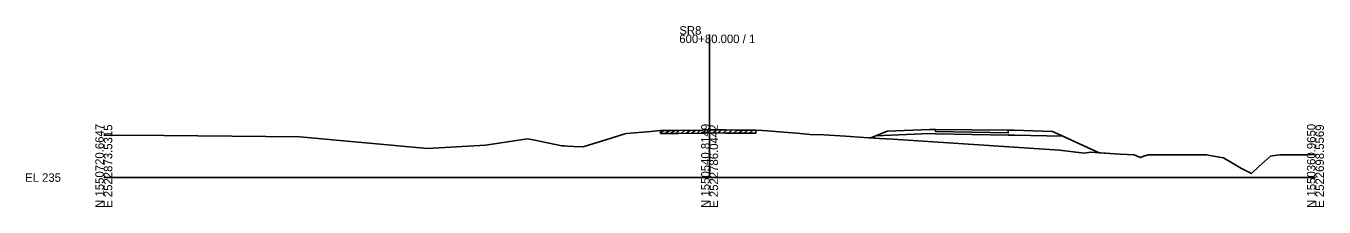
# Model space of a CAD drawing. Extents: x -26 to 2803, y -10 to 19537.
# Drawn here: x -25.7 to 402.8, y 8990.3 to 9049.9 of the extents above; entities that cross this region are included whole.
import ezdxf

# ---------------------------------------------------------------- set-up
doc = ezdxf.new("R2010")
doc.units = 0
for name, color, linetype in [('50', 7, 'Continuous'), ('XS_CELL', 7, 'Continuous'), ('XS_M_MULTI', 7, 'Continuous'), ('XS_M_SHAPES_EARTHWORK', 7, 'Continuous'), ('XS_P_FINISHED_GRADE', 7, 'Continuous'), ('XS_P_SUBGRADE_GRANULAR', 7, 'Continuous'), ('XS_P_SUBGRADE_PAVEMENT', 7, 'Continuous'), ('XS_X_GROUND', 7, 'Continuous')]:
    doc.layers.add(name, color=color, linetype=linetype)

msp = doc.modelspace()

# ---------------------------------------------------------------- linework, layer by layer
at = {"layer": '50'}
for p, q in [((183.74, 9014.48), (184.91, 9015.5)), ((183.74, 9014.48), (183.74, 9015.48)), ((183.74, 9014.48), (189.6, 9014.56)), ((185.47, 9014.5), (186.64, 9015.52)), ((187.2, 9014.53), (188.37, 9015.54)), ((188.93, 9014.55), (190.1, 9015.57)), ((189.6, 9014.56), (197.81, 9014.67)), ((190.66, 9014.57), (191.83, 9015.59)), ((192.39, 9014.6), (193.56, 9015.61)), ((194.12, 9014.62), (195.29, 9015.64)), ((195.85, 9014.65), (197.02, 9015.66)), ((197.58, 9014.67), (198.75, 9015.68)), ((197.81, 9014.67), (198.84, 9014.69)), ((198.84, 9014.69), (199.58, 9014.7)), ((199.31, 9014.69), (200.46, 9015.69)), ((199.58, 9014.7), (200, 9014.69)), ((200, 9014.69), (205.27, 9014.68)), ((201.04, 9014.69), (202.18, 9015.69)), ((202.77, 9014.69), (203.91, 9015.68)), ((204.5, 9014.68), (205.64, 9015.68)), ((205.27, 9014.68), (209, 9014.67)), ((206.22, 9014.67), (207.37, 9015.67)), ((207.95, 9014.67), (209.1, 9015.67)), ((209, 9014.67), (211.46, 9014.66)), ((209.68, 9014.66), (210.83, 9015.66)), ((211.41, 9014.66), (212.56, 9015.66)), ((211.46, 9014.66), (215.27, 9014.65)), ((213.14, 9014.65), (214.29, 9015.65)), ((215.27, 9015.65), (215.27, 9014.65))]:
    msp.add_line(p, q, dxfattribs=at)
at = {"layer": 'XS_CELL'}
for p, q in [((200, 9000), (200, 9047.09)), ((0, 9000), (200, 9000)), ((200, 9000), (400, 9000))]:
    msp.add_line(p, q, dxfattribs=at)
at = {"layer": 'XS_M_MULTI'}
for p, q in [((253.19, 9013.08), (258.62, 9015.34)), ((258.62, 9015.34), (272.75, 9015.83)), ((272.75, 9015.83), (286.6, 9015.7)), ((286.6, 9015.7), (300.46, 9015.59)), ((300.46, 9015.59), (313.17, 9015.15)), ((313.17, 9015.15), (328.58, 9008.19))]:
    msp.add_line(p, q, dxfattribs=at)
for points in [[(0, 9014.01), (19.82, 9013.88), (64.74, 9013.38), (106.88, 9009.59), (126.02, 9010.7), (139.91, 9012.73), (141.73, 9012.46), (151.22, 9010.47), (151.57, 9010.45), (152.11, 9010.42), (153.06, 9010.37), (155.18, 9010.25), (158.31, 9010.08), (160.39, 9010.76), (165.75, 9012.47), (171.7, 9014.3), (172.09, 9014.42), (172.59, 9014.57), (180.57, 9015.22), (183.74, 9015.48), (189.6, 9015.56), (197.81, 9015.67), (198.84, 9015.69), (199.58, 9015.7), (200, 9015.69), (205.27, 9015.68), (209, 9015.67), (211.46, 9015.66), (215.27, 9015.65), (217.43, 9015.48), (219.06, 9015.35), (223.08, 9015.04), (228.76, 9014.62), (233.22, 9014.23), (237.68, 9014.06), (244.91, 9013.6), (250.96, 9013.22), (253.19, 9013.08)], [(328.58, 9008.19), (335.55, 9007.76), (340.21, 9007.48), (342.21, 9006.57), (343.01, 9006.91), (344.82, 9007.5), (349.87, 9007.44), (364.15, 9007.48), (365.19, 9007.29), (369.66, 9006.49), (375.63, 9003.02), (378.86, 9001.3), (381.29, 9003.69), (385.22, 9007.06), (385.73, 9007.13), (388.27, 9007.49), (397.2, 9007.52), (400, 9007.58)]]:
    msp.add_lwpolyline(points, dxfattribs=at)
at = {"layer": 'XS_M_SHAPES_EARTHWORK'}
for points in [[(256.09, 9012.9), (260.5, 9012.62), (315.52, 9009.01), (323.65, 9008.06), (325.89, 9008.35), (328.58, 9008.19), (316.58, 9013.61), (300.6, 9013.92), (298.6, 9013.96), (286.6, 9014.2), (274.6, 9014.44), (272.6, 9014.48), (254.86, 9013.77), (253.19, 9013.08)], [(300.6, 9013.92), (316.58, 9013.61), (313.17, 9015.15), (300.46, 9015.59), (298.6, 9015.6), (298.6, 9014.71), (286.6, 9014.95), (274.6, 9015.19), (274.6, 9015.81), (272.75, 9015.83), (258.62, 9015.34), (254.86, 9013.77), (272.6, 9014.48), (274.6, 9014.44), (286.6, 9014.2), (298.6, 9013.96)], [(286.6, 9014.95), (298.6, 9014.71), (298.6, 9015.6), (286.6, 9015.7), (274.6, 9015.81), (274.6, 9015.19)]]:
    msp.add_lwpolyline(points, close=True, dxfattribs=at)
at = {"layer": 'XS_P_FINISHED_GRADE'}
for p, q in [((258.62, 9015.34), (253.19, 9013.08)), ((272.75, 9015.83), (258.62, 9015.34)), ((272.75, 9015.83), (286.6, 9015.7)), ((286.6, 9015.7), (300.46, 9015.59)), ((300.46, 9015.59), (313.17, 9015.15)), ((313.17, 9015.15), (328.58, 9008.19))]:
    msp.add_line(p, q, dxfattribs=at)
at = {"layer": 'XS_P_SUBGRADE_GRANULAR'}
for p, q in [((272.6, 9014.48), (254.86, 9013.77)), ((274.6, 9014.44), (272.6, 9014.48)), ((274.6, 9014.44), (286.6, 9014.2)), ((286.6, 9014.2), (298.6, 9013.96)), ((298.6, 9013.96), (300.6, 9013.92)), ((300.6, 9013.92), (316.58, 9013.61))]:
    msp.add_line(p, q, dxfattribs=at)
at = {"layer": 'XS_P_SUBGRADE_PAVEMENT'}
for p, q in [((274.6, 9015.19), (274.6, 9015.81)), ((274.6, 9015.19), (286.6, 9014.95)), ((286.6, 9014.95), (298.6, 9014.71)), ((298.6, 9014.71), (298.6, 9015.6))]:
    msp.add_line(p, q, dxfattribs=at)
at = {"layer": 'XS_X_GROUND'}
msp.add_lwpolyline([(0, 9014.01), (19.82, 9013.88), (64.74, 9013.38), (106.88, 9009.59), (126.02, 9010.7), (139.91, 9012.73), (141.73, 9012.46), (151.22, 9010.47), (151.57, 9010.45), (152.11, 9010.42), (153.06, 9010.37), (155.18, 9010.25), (158.31, 9010.08), (160.39, 9010.76), (165.75, 9012.47), (171.7, 9014.3), (172.09, 9014.42), (172.59, 9014.57), (180.57, 9015.22), (183.74, 9015.48), (189.6, 9015.56), (197.81, 9015.67), (198.84, 9015.69), (199.58, 9015.7), (200, 9015.69), (205.27, 9015.68), (209, 9015.67), (211.46, 9015.66), (215.27, 9015.65), (217.43, 9015.48), (219.06, 9015.35), (223.08, 9015.04), (228.76, 9014.62), (233.22, 9014.23), (237.68, 9014.06), (244.91, 9013.6), (250.96, 9013.22), (256.09, 9012.9), (260.5, 9012.62), (315.52, 9009.01), (323.65, 9008.06), (325.89, 9008.35), (335.55, 9007.76), (340.21, 9007.48), (342.21, 9006.57), (343.01, 9006.91), (344.82, 9007.5), (349.87, 9007.44), (364.15, 9007.48), (365.19, 9007.29), (369.66, 9006.49), (375.63, 9003.02), (378.86, 9001.3), (381.29, 9003.69), (385.22, 9007.06), (385.73, 9007.13), (388.27, 9007.49), (397.2, 9007.52), (400, 9007.58)], dxfattribs=at)

# ---------------------------------------------------------------- texts
at = {"layer": 'XS_CELL'}
for s, p in [('SR8', (190, 9047.09)), ('600+80.000 / 1', (190, 9044.29)), ('EL 235', (-26, 8998.6))]:
    msp.add_text(s, height=2.8, dxfattribs=at).set_placement(p)
for s, p in [('N 1550720.6647', (0, 8990)), ('E 2522873.5315', (2.8, 8990)), ('N 1550540.8149', (200, 8990)), ('E 2522786.0442', (202.8, 8990)), ('N 1550360.9650', (400, 8990)), ('E 2522698.5569', (402.8, 8990))]:
    msp.add_text(s, height=2.8, rotation=90, dxfattribs=at).set_placement(p)

doc.saveas('drawing.dxf')
